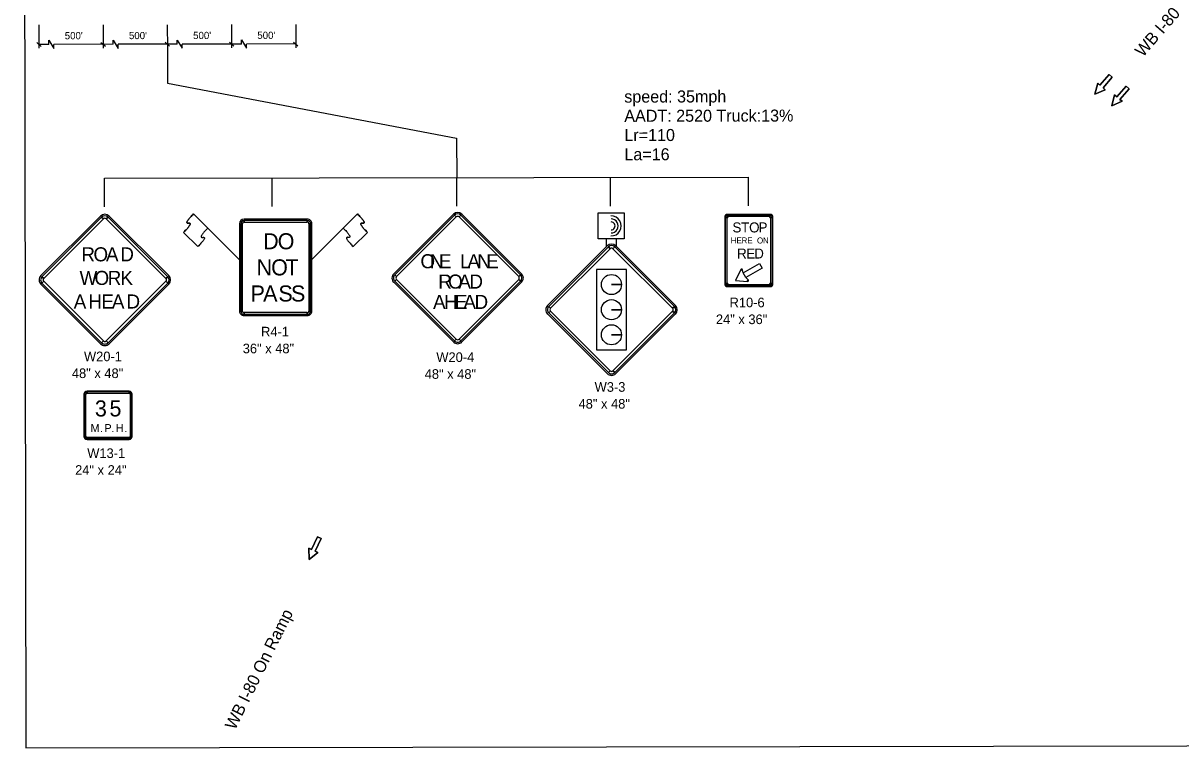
# Model space of a CAD drawing. Extents: x 16513048 to 16518780, y 7009856 to 7010869.
# Drawn here: x 16515047 to 16515769, y 7009856 to 7010308 of the extents above; entities that cross this region are included whole.
import ezdxf

# ---------------------------------------------------------------- set-up
doc = ezdxf.new("R2010")
doc.units = 0
for name, color, linetype in [('Dimensions', 7, 'Continuous'), ('dsnNonPlotable', 7, 'Continuous'), ('dsnStdLabel', 7, 'Continuous'), ('Level 2', 7, 'Continuous'), ('Level 5', 7, 'Continuous'), ('NamedBoundary', 7, 'Continuous')]:
    doc.layers.add(name, color=color, linetype=linetype)

msp = doc.modelspace()

# ---------------------------------------------------------------- linework, layer by layer
at = {"layer": 'dsnStdLabel'}
for p, q in [((16515095.65, 7010187.98), (16515058.47, 7010150.8)), ((16515096.31, 7010187.31), (16515097.42, 7010186.21)), ((16515099.19, 7010186.21), (16515100.3, 7010187.31)), ((16515138.14, 7010150.8), (16515100.96, 7010187.98)), ((16515182.3, 7010160.59), (16515153.59, 7010189.28)), ((16515153.59, 7010189.28), (16515162.44, 7010180.43)), ((16515182.23, 7010183.19), (16515182.23, 7010128.73)), ((16515183.01, 7010183.19), (16515184.11, 7010183.19)), ((16515224.48, 7010186), (16515185.05, 7010186)), ((16515185.05, 7010184.13), (16515185.05, 7010185.22)), ((16515224.48, 7010185.22), (16515224.48, 7010184.13)), ((16515225.42, 7010183.19), (16515226.51, 7010183.19)), ((16515227.01, 7010160.59), (16515255.71, 7010189.29)), ((16515227.29, 7010128.73), (16515227.29, 7010183.19)), ((16515255.71, 7010189.29), (16515246.85, 7010180.43)), ((16515315.5, 7010189.14), (16515278.32, 7010151.96)), ((16515316.17, 7010188.47), (16515317.27, 7010187.37)), ((16515319.04, 7010187.37), (16515320.15, 7010188.47)), ((16515357.99, 7010151.96), (16515320.81, 7010189.14)), ((16515484.59, 7010187.12), (16515486.47, 7010187.12)), ((16515485.06, 7010187.12), (16515485.84, 7010187.12)), ((16515486.47, 7010187.12), (16515486.47, 7010189)), ((16515486.47, 7010187.75), (16515486.47, 7010188.53)), ((16515512.75, 7010189), (16515512.75, 7010187.12)), ((16515512.75, 7010188.53), (16515512.75, 7010187.75)), ((16515512.75, 7010187.12), (16515514.63, 7010187.12)), ((16515513.38, 7010187.12), (16515514.16, 7010187.12)), ((16515156.25, 7010168.92), (16515147.39, 7010177.77)), ((16515253.06, 7010168.92), (16515261.91, 7010177.78)), ((16515411.4, 7010169.38), (16515374.22, 7010132.2)), ((16515453.89, 7010132.2), (16515416.71, 7010169.38)), ((16515412.06, 7010168.71), (16515413.17, 7010167.61)), ((16515414.94, 7010167.61), (16515416.04, 7010168.71)), ((16515494.53, 7010154.59), (16515495.09, 7010154.29)), ((16515495.09, 7010154.29), (16515495.7, 7010154.43)), ((16515060.24, 7010149.03), (16515059.14, 7010150.14)), ((16515059.14, 7010146.15), (16515060.24, 7010147.26)), ((16515137.47, 7010150.14), (16515136.37, 7010149.03)), ((16515136.37, 7010147.26), (16515137.47, 7010146.15)), ((16515280.09, 7010150.19), (16515278.99, 7010151.3)), ((16515278.99, 7010147.31), (16515280.09, 7010148.42)), ((16515357.32, 7010151.3), (16515356.22, 7010150.19)), ((16515356.22, 7010148.42), (16515357.32, 7010147.31)), ((16515498.84, 7010147.79), (16515498.82, 7010147.16)), ((16515499.27, 7010148.25), (16515498.84, 7010147.79)), ((16515058.47, 7010145.49), (16515095.65, 7010108.31)), ((16515100.96, 7010108.31), (16515138.14, 7010145.49)), ((16515278.32, 7010146.65), (16515315.5, 7010109.47)), ((16515320.81, 7010109.47), (16515357.99, 7010146.65)), ((16515420.27, 7010145.23), (16515414.01, 7010145.23)), ((16515414.01, 7010145.23), (16515420.27, 7010145.23)), ((16515486.47, 7010145.81), (16515484.59, 7010145.81)), ((16515485.84, 7010145.81), (16515485.06, 7010145.81)), ((16515486.47, 7010143.94), (16515486.47, 7010145.81)), ((16515486.47, 7010144.41), (16515486.47, 7010145.19)), ((16515514.63, 7010145.81), (16515512.75, 7010145.81)), ((16515512.75, 7010145.81), (16515512.75, 7010143.94)), ((16515512.75, 7010145.19), (16515512.75, 7010144.41)), ((16515514.16, 7010145.81), (16515513.38, 7010145.81)), ((16515184.11, 7010128.73), (16515183.01, 7010128.73)), ((16515185.05, 7010126.7), (16515185.05, 7010127.8)), ((16515185.05, 7010125.92), (16515224.48, 7010125.92)), ((16515224.48, 7010127.8), (16515224.48, 7010126.7)), ((16515226.51, 7010128.73), (16515225.42, 7010128.73)), ((16515374.22, 7010126.89), (16515411.4, 7010089.71)), ((16515375.99, 7010130.43), (16515374.88, 7010131.53)), ((16515374.88, 7010127.55), (16515375.99, 7010128.66)), ((16515420.27, 7010129.58), (16515414.01, 7010129.58)), ((16515414.01, 7010129.58), (16515420.27, 7010129.58)), ((16515416.71, 7010089.71), (16515453.89, 7010126.89)), ((16515453.22, 7010131.53), (16515452.12, 7010130.43)), ((16515452.12, 7010128.66), (16515453.22, 7010127.55)), ((16515317.27, 7010111.24), (16515316.17, 7010110.14)), ((16515320.15, 7010110.14), (16515319.04, 7010111.24)), ((16515420.27, 7010113.93), (16515414.01, 7010113.93)), ((16515414.01, 7010113.93), (16515420.27, 7010113.93)), ((16515097.42, 7010110.08), (16515096.31, 7010108.98)), ((16515100.3, 7010108.98), (16515099.19, 7010110.08)), ((16515413.17, 7010091.48), (16515412.06, 7010090.37)), ((16515416.04, 7010090.37), (16515414.94, 7010091.48)), ((16515085.31, 7010076.88), (16515085.31, 7010050.59)), ((16515085.78, 7010076.88), (16515086.56, 7010076.88)), ((16515113.48, 7010078.76), (16515087.19, 7010078.76)), ((16515087.19, 7010077.51), (16515087.19, 7010078.29)), ((16515113.48, 7010078.29), (16515113.48, 7010077.51)), ((16515114.1, 7010076.88), (16515114.88, 7010076.88)), ((16515115.35, 7010050.59), (16515115.35, 7010076.88)), ((16515086.56, 7010050.59), (16515085.78, 7010050.59)), ((16515087.19, 7010049.19), (16515087.19, 7010049.97)), ((16515087.19, 7010048.72), (16515113.48, 7010048.72)), ((16515113.48, 7010049.97), (16515113.48, 7010049.19)), ((16515114.88, 7010050.59), (16515114.1, 7010050.59))]:
    msp.add_line(p, q, dxfattribs=at)
for points in [[(16515096.31, 7010187.31), (16515059.14, 7010150.14), (16515060.24, 7010149.03), (16515097.42, 7010186.21), (16515096.31, 7010187.31)], [(16515137.47, 7010150.14), (16515100.3, 7010187.31), (16515099.19, 7010186.21), (16515136.37, 7010149.03), (16515137.47, 7010150.14)], [(16515183.01, 7010183.19), (16515183.01, 7010128.73), (16515184.11, 7010128.73), (16515184.11, 7010183.19), (16515183.01, 7010183.19)], [(16515224.48, 7010185.22), (16515185.05, 7010185.22), (16515185.05, 7010184.13), (16515224.48, 7010184.13), (16515224.48, 7010185.22)], [(16515226.51, 7010128.73), (16515226.51, 7010183.19), (16515225.42, 7010183.19), (16515225.42, 7010128.73), (16515226.51, 7010128.73)], [(16515316.17, 7010188.47), (16515278.99, 7010151.3), (16515280.09, 7010150.19), (16515317.27, 7010187.37), (16515316.17, 7010188.47)], [(16515357.32, 7010151.3), (16515320.15, 7010188.47), (16515319.04, 7010187.37), (16515356.22, 7010150.19), (16515357.32, 7010151.3)], [(16515486.47, 7010143.94), (16515512.75, 7010143.94), (16515512.75, 7010145.81), (16515514.63, 7010145.81), (16515514.63, 7010187.12), (16515512.75, 7010187.12), (16515512.75, 7010189), (16515486.47, 7010189), (16515486.47, 7010187.12), (16515484.59, 7010187.12), (16515484.59, 7010145.81), (16515486.47, 7010145.81), (16515486.47, 7010143.94)], [(16515485.84, 7010187.12), (16515485.84, 7010145.81), (16515485.06, 7010145.81), (16515485.06, 7010187.12), (16515485.84, 7010187.12)], [(16515512.75, 7010187.75), (16515486.47, 7010187.75), (16515486.47, 7010188.53), (16515512.75, 7010188.53), (16515512.75, 7010187.75)], [(16515513.38, 7010145.81), (16515513.38, 7010187.12), (16515514.16, 7010187.12), (16515514.16, 7010145.81), (16515513.38, 7010145.81)], [(16515412.06, 7010168.71), (16515374.88, 7010131.53), (16515375.99, 7010130.43), (16515413.17, 7010167.61), (16515412.06, 7010168.71)], [(16515453.22, 7010131.53), (16515416.04, 7010168.71), (16515414.94, 7010167.61), (16515452.12, 7010130.43), (16515453.22, 7010131.53)], [(16515423.43, 7010154.55), (16515404.67, 7010154.55), (16515404.67, 7010104.53), (16515423.43, 7010104.53), (16515423.43, 7010154.55)], [(16515491.27, 7010147.76), (16515498.82, 7010147.16), (16515498.84, 7010147.79), (16515499.27, 7010148.25), (16515497.78, 7010149.62), (16515496.14, 7010152.46), (16515495.7, 7010154.43), (16515495.09, 7010154.29), (16515494.53, 7010154.59), (16515491.27, 7010147.76)], [(16515506.31, 7010158.33), (16515507.95, 7010155.49), (16515497.78, 7010149.62), (16515496.14, 7010152.46), (16515506.31, 7010158.33)], [(16515059.14, 7010146.15), (16515096.31, 7010108.98), (16515097.42, 7010110.08), (16515060.24, 7010147.26), (16515059.14, 7010146.15)], [(16515100.3, 7010108.98), (16515137.47, 7010146.15), (16515136.37, 7010147.26), (16515099.19, 7010110.08), (16515100.3, 7010108.98)], [(16515278.99, 7010147.31), (16515316.17, 7010110.14), (16515317.27, 7010111.24), (16515280.09, 7010148.42), (16515278.99, 7010147.31)], [(16515320.15, 7010110.14), (16515357.32, 7010147.31), (16515356.22, 7010148.42), (16515319.04, 7010111.24), (16515320.15, 7010110.14)], [(16515486.47, 7010145.19), (16515512.75, 7010145.19), (16515512.75, 7010144.41), (16515486.47, 7010144.41), (16515486.47, 7010145.19)], [(16515185.05, 7010126.7), (16515224.48, 7010126.7), (16515224.48, 7010127.8), (16515185.05, 7010127.8), (16515185.05, 7010126.7)], [(16515374.88, 7010127.55), (16515412.06, 7010090.37), (16515413.17, 7010091.48), (16515375.99, 7010128.66), (16515374.88, 7010127.55)], [(16515416.04, 7010090.37), (16515453.22, 7010127.55), (16515452.12, 7010128.66), (16515414.94, 7010091.48), (16515416.04, 7010090.37)], [(16515085.78, 7010076.88), (16515085.78, 7010050.59), (16515086.56, 7010050.59), (16515086.56, 7010076.88), (16515085.78, 7010076.88)], [(16515113.48, 7010078.29), (16515087.19, 7010078.29), (16515087.19, 7010077.51), (16515113.48, 7010077.51), (16515113.48, 7010078.29)], [(16515114.88, 7010050.59), (16515114.88, 7010076.88), (16515114.1, 7010076.88), (16515114.1, 7010050.59), (16515114.88, 7010050.59)], [(16515087.19, 7010049.19), (16515113.48, 7010049.19), (16515113.48, 7010049.97), (16515087.19, 7010049.97), (16515087.19, 7010049.19)]]:
    msp.add_lwpolyline(points, close=True, dxfattribs=at)
for centre in [(16515414.01, 7010145.23), (16515414.01, 7010129.58), (16515414.01, 7010113.93)]:
    msp.add_circle(centre, 6.26, dxfattribs=at)
for centre, radius, start, end in [((16515098.3, 7010185.32), 3.76, 44.99999, 134.99974), ((16515098.3, 7010185.32), 2.82, 44.99999, 134.99974), ((16515098.3, 7010185.32), 1.25, 44.99999, 134.99974), ((16515185.05, 7010183.19), 2.82, 90.00021, 179.99985), ((16515185.05, 7010183.19), 2.03, 90.00021, 179.99985), ((16515185.05, 7010183.19), 0.939, 90.00021, 179.99985), ((16515224.48, 7010183.19), 2.82, 0, 90.00021), ((16515224.48, 7010183.19), 2.03, 0, 90.00021), ((16515224.48, 7010183.19), 0.939, 0, 90.00021), ((16515318.16, 7010186.48), 3.76, 44.99999, 134.99974), ((16515318.16, 7010186.48), 2.82, 44.99999, 134.99974), ((16515318.16, 7010186.48), 1.25, 44.99999, 134.99974), ((16515486.47, 7010187.12), 1.88, 90.00021, 179.99985), ((16515486.47, 7010187.12), 1.41, 90.00021, 179.99985), ((16515486.47, 7010187.12), 0.626, 90.00021, 179.99985), ((16515512.75, 7010187.12), 1.88, 0, 90.00021), ((16515512.75, 7010187.12), 1.41, 0, 90.00021), ((16515512.75, 7010187.12), 0.626, 0, 90.00021), ((16515414.05, 7010166.72), 3.76, 44.99999, 134.99974), ((16515414.05, 7010166.72), 2.82, 44.99999, 134.99974), ((16515414.05, 7010166.72), 1.25, 44.99999, 134.99974), ((16515495.09, 7010154.29), 0.626, 12.62232, 152.27557), ((16515061.13, 7010148.14), 3.76, 134.99974, 224.99995), ((16515061.13, 7010148.14), 2.82, 134.99974, 224.99995), ((16515061.13, 7010148.14), 1.25, 134.99974, 224.99995), ((16515135.48, 7010148.14), 1.25, 315.00016, 44.9998), ((16515135.48, 7010148.14), 2.82, 315.00016, 44.9998), ((16515135.48, 7010148.14), 3.76, 315.00016, 44.9998), ((16515280.98, 7010149.31), 3.76, 134.99974, 224.99995), ((16515280.98, 7010149.31), 2.82, 134.99974, 224.99995), ((16515280.98, 7010149.31), 1.25, 134.99974, 224.99995), ((16515355.33, 7010149.31), 1.25, 315.00016, 44.9998), ((16515355.33, 7010149.31), 2.82, 315.00016, 44.9998), ((16515355.33, 7010149.31), 3.76, 315.00016, 44.9998), ((16515498.84, 7010147.79), 0.626, 267.72427, 47.37758), ((16515486.47, 7010145.81), 1.88, 179.99985, 270.00006), ((16515486.47, 7010145.81), 1.41, 179.99985, 270.00006), ((16515486.47, 7010145.81), 0.626, 179.99985, 270.00006), ((16515512.75, 7010145.81), 1.88, 270.00006, 0.00027), ((16515512.75, 7010145.81), 1.41, 270.00006, 0.00027), ((16515512.75, 7010145.81), 0.626, 270.00006, 0.00027), ((16515185.05, 7010128.73), 2.82, 179.99985, 270.00006), ((16515185.05, 7010128.73), 2.03, 179.99985, 270.00006), ((16515185.05, 7010128.73), 0.939, 179.99985, 270.00006), ((16515224.48, 7010128.73), 2.82, 270.00006, 0.00027), ((16515224.48, 7010128.73), 2.03, 270.00006, 0.00027), ((16515224.48, 7010128.73), 0.939, 270.00006, 0.00027), ((16515376.88, 7010129.54), 3.76, 134.99974, 224.99995), ((16515376.88, 7010129.54), 2.82, 134.99974, 224.99995), ((16515376.88, 7010129.54), 1.25, 134.99974, 224.99995), ((16515451.23, 7010129.54), 1.25, 315.00016, 44.9998), ((16515451.23, 7010129.54), 2.82, 315.00016, 44.9998), ((16515451.23, 7010129.54), 3.76, 315.00016, 44.9998), ((16515318.16, 7010112.13), 1.25, 224.99995, 315.00016), ((16515098.3, 7010110.97), 3.76, 224.99995, 315.00016), ((16515098.3, 7010110.97), 2.82, 224.99995, 315.00016), ((16515098.3, 7010110.97), 1.25, 224.99995, 315.00016), ((16515318.16, 7010112.13), 3.76, 224.99995, 315.00016), ((16515318.16, 7010112.13), 2.82, 224.99995, 315.00016), ((16515414.05, 7010092.37), 3.76, 224.99995, 315.00016), ((16515414.05, 7010092.37), 2.82, 224.99995, 315.00016), ((16515414.05, 7010092.37), 1.25, 224.99995, 315.00016), ((16515087.19, 7010076.88), 1.88, 90.00021, 179.99985), ((16515087.19, 7010076.88), 1.41, 90.00021, 179.99985), ((16515087.19, 7010076.88), 0.626, 90.00021, 179.99985), ((16515113.48, 7010076.88), 1.88, 0, 90.00021), ((16515113.48, 7010076.88), 1.41, 0, 90.00021), ((16515113.48, 7010076.88), 0.626, 0, 90.00021), ((16515087.19, 7010050.59), 1.88, 179.99985, 270.00006), ((16515087.19, 7010050.59), 1.41, 179.99985, 270.00006), ((16515087.19, 7010050.59), 0.626, 179.99985, 270.00006), ((16515113.48, 7010050.59), 1.88, 270.00006, 0.00027), ((16515113.48, 7010050.59), 1.41, 270.00006, 0.00027), ((16515113.48, 7010050.59), 0.626, 270.00006, 0.00027)]:
    msp.add_arc(centre, radius, start, end, dxfattribs=at)
for points in [[(16515147.39, 7010177.77), (16515153.59, 7010183.96), (16515147.39, 7010183.08), (16515153.59, 7010189.28)], [(16515261.91, 7010177.78), (16515255.71, 7010183.97), (16515261.91, 7010183.09), (16515255.71, 7010189.29)], [(16515162.44, 7010180.43), (16515156.25, 7010174.23), (16515162.44, 7010175.11), (16515156.25, 7010168.92)], [(16515246.85, 7010180.43), (16515253.05, 7010174.23), (16515246.86, 7010175.12), (16515253.06, 7010168.92)]]:
    msp.add_open_spline(points, degree=2, dxfattribs=at)
at = {"layer": 'Level 2'}
for p, q in [((16515057.23, 7010307.08), (16515057.26, 7010292.53)), ((16515097.23, 7010307.15), (16515097.25, 7010292.6)), ((16515137.23, 7010307.22), (16515137.25, 7010292.66)), ((16515177.23, 7010307.29), (16515177.25, 7010292.73)), ((16515217.23, 7010307.36), (16515217.25, 7010292.8)), ((16515055.88, 7010296.13), (16515058.63, 7010293.75)), ((16515063.42, 7010294.95), (16515057.25, 7010294.94)), ((16515103.42, 7010295.02), (16515066.58, 7010294.96)), ((16515095.88, 7010296.2), (16515098.63, 7010293.82)), ((16515143.42, 7010295.09), (16515106.58, 7010295.03)), ((16515135.88, 7010296.27), (16515138.63, 7010293.89)), ((16515137.25, 7010292.66), (16515137.29, 7010270.71)), ((16515183.42, 7010295.16), (16515146.58, 7010295.1)), ((16515175.88, 7010296.34), (16515178.63, 7010293.96)), ((16515217.25, 7010295.22), (16515186.58, 7010295.17)), ((16515215.88, 7010296.41), (16515218.63, 7010294.03)), ((16515137.29, 7010270.71), (16515317.53, 7010236.52)), ((16515317.53, 7010236.52), (16515317.57, 7010211.85)), ((16515098.08, 7010211.47), (16515499.38, 7010212.17)), ((16515413.49, 7010194.22), (16515413.46, 7010212.02)), ((16515499.41, 7010194.37), (16515499.38, 7010212.17)), ((16515098.11, 7010193.67), (16515098.08, 7010211.47)), ((16515202.54, 7010193.85), (16515202.51, 7010211.65)), ((16515317.6, 7010194.05), (16515317.57, 7010211.85)), ((16515410.63, 7010173.66), (16515410.63, 7010168.65)), ((16515416.89, 7010173.66), (16515416.89, 7010168.65))]:
    msp.add_line(p, q, dxfattribs=at)
for points in [[(16515063.42, 7010294.96), (16515063.42, 7010297.51), (16515066.58, 7010292.4), (16515066.58, 7010294.96)], [(16515103.42, 7010295.03), (16515103.42, 7010297.58), (16515106.58, 7010292.47), (16515106.58, 7010295.03)], [(16515143.42, 7010295.1), (16515143.42, 7010297.65), (16515146.58, 7010292.54), (16515146.58, 7010295.1)], [(16515183.42, 7010295.17), (16515183.42, 7010297.72), (16515186.58, 7010292.61), (16515186.58, 7010295.17)]]:
    msp.add_lwpolyline(points, dxfattribs=at)
for points in [[(16515724.1, 7010276.23), (16515726, 7010274.6), (16515720.31, 7010267.95), (16515721.73, 7010266.73), (16515715.29, 7010264.02), (16515716.99, 7010270.8), (16515718.41, 7010269.58)], [(16515734.66, 7010268.97), (16515736.56, 7010267.34), (16515730.86, 7010260.7), (16515732.29, 7010259.48), (16515725.85, 7010256.76), (16515727.54, 7010263.54), (16515728.96, 7010262.32)], [(16515405.62, 7010173.66), (16515405.62, 7010189.93), (16515421.89, 7010189.93), (16515421.89, 7010173.66)], [(16515230.75, 7009987.95), (16515233.02, 7009986.9), (16515229.34, 7009978.96), (16515231.04, 7009978.17), (16515225.57, 7009973.81), (16515225.37, 7009980.8), (16515227.07, 7009980.01)]]:
    msp.add_lwpolyline(points, close=True, dxfattribs=at)
for radius in [6.26, 6.26, 4.38, 2.5]:
    msp.add_arc((16515413.76, 7010181.79), radius, 269.40414, 90.54446, dxfattribs=at)
at = {"layer": 'Level 5'}
for p, q in [((16515147.39, 7010177.77), (16515156.25, 7010168.92)), ((16515261.91, 7010177.78), (16515253.06, 7010168.92))]:
    msp.add_line(p, q, dxfattribs=at)
for points in [[(16515718.41, 7010269.58), (16515716.99, 7010270.8), (16515715.29, 7010264.02), (16515721.73, 7010266.73), (16515720.31, 7010267.95), (16515726, 7010274.6), (16515724.1, 7010276.23), (16515718.41, 7010269.58)], [(16515728.96, 7010262.32), (16515727.54, 7010263.54), (16515725.85, 7010256.76), (16515732.29, 7010259.48), (16515730.86, 7010260.7), (16515736.56, 7010267.34), (16515734.66, 7010268.97), (16515728.96, 7010262.32)], [(16515227.07, 7009980.01), (16515225.37, 7009980.8), (16515225.57, 7009973.81), (16515231.04, 7009978.17), (16515229.34, 7009978.96), (16515233.02, 7009986.9), (16515230.75, 7009987.95), (16515227.07, 7009980.01)]]:
    msp.add_lwpolyline(points, dxfattribs=at)
for points in [[(16515153.59, 7010189.28), (16515147.39, 7010183.08), (16515153.59, 7010183.96), (16515147.39, 7010177.77)], [(16515255.71, 7010189.29), (16515261.91, 7010183.09), (16515255.71, 7010183.97), (16515261.91, 7010177.78)], [(16515162.44, 7010180.43), (16515156.25, 7010174.23), (16515162.44, 7010175.11), (16515156.25, 7010168.92)], [(16515246.85, 7010180.43), (16515253.05, 7010174.23), (16515246.86, 7010175.12), (16515253.06, 7010168.92)]]:
    msp.add_open_spline(points, degree=2, dxfattribs=at)
at = {"layer": 'NamedBoundary'}
msp.add_lwpolyline([(16515047.4, 7010866.4), (16515049.16, 7009856.4), (16516616.66, 7009859.13), (16516614.9, 7010869.13)], close=True, dxfattribs=at)

# ---------------------------------------------------------------- texts
at = {"layer": 'Dimensions'}
for s, rotation, p in [('WB I-80', 49.18036, (16515745.21, 7010286.65)), ('WB I-80 On Ramp', 63.63415, (16515179.45, 7009867.1))]:
    msp.add_text(s, height=7.5, rotation=rotation, dxfattribs=at).set_placement(p)
at = {"layer": 'dsnNonPlotable'}
for s, p in [('speed: 35mph', (16515421.99, 7010258.68)), ('AADT: 2520 Truck:13%', (16515422.01, 7010246.68)), ('Lr=110', (16515422.04, 7010234.68)), ('La=16', (16515422.06, 7010222.68))]:
    msp.add_text(s, height=7.5, rotation=0.09989, dxfattribs=at).set_placement(p)
at = {"layer": 'dsnStdLabel'}
for s, height, p in [('S', 6.26, (16515489.37, 7010177.74)), ('T', 6.26, (16515494.76, 7010177.74)), ('O', 6.26, (16515499.76, 7010177.74)), ('P', 6.26, (16515505.64, 7010177.74)), ('D', 10.01, (16515196.94, 7010167.23)), ('O', 10.01, (16515206.01, 7010167.23)), ('H', 3.76, (16515488.33, 7010170.85)), ('E', 3.76, (16515491.91, 7010170.85)), ('R', 3.76, (16515495.05, 7010170.85)), ('E', 3.76, (16515498.62, 7010170.85)), ('O', 3.76, (16515504.67, 7010170.85)), ('N', 3.76, (16515508.37, 7010170.85)), ('R', 8.76, (16515083.7, 7010159.72)), ('O', 8.76, (16515091.22, 7010159.72)), ('A', 8.76, (16515099.01, 7010159.72)), ('D', 8.76, (16515107.96, 7010159.72)), ('O', 8.76, (16515294.98, 7010155.41)), ('N', 8.76, (16515300.88, 7010155.41)), ('E', 8.76, (16515306.5, 7010155.41)), ('L', 8.76, (16515319.64, 7010155.41)), ('A', 8.76, (16515324.25, 7010155.41)), ('N', 8.76, (16515330.39, 7010155.41)), ('E', 8.76, (16515336.01, 7010155.41)), ('R', 6.26, (16515492.26, 7010161.46)), ('E', 6.26, (16515497.93, 7010161.46)), ('D', 6.26, (16515502.92, 7010161.46)), ('N', 10.01, (16515192.87, 7010150.95)), ('O', 10.01, (16515201.95, 7010150.95)), ('T', 10.01, (16515210.86, 7010150.95)), ('W', 8.76, (16515082.56, 7010145.01)), ('O', 8.76, (16515091.87, 7010145.01)), ('R', 8.76, (16515100.09, 7010145.01)), ('K', 8.76, (16515108.03, 7010145.01)), ('R', 8.76, (16515306.05, 7010142.73)), ('O', 8.76, (16515312.2, 7010142.73)), ('A', 8.76, (16515318.63, 7010142.73)), ('D', 8.76, (16515325.47, 7010142.73)), ('P', 10.01, (16515189.11, 7010134.68)), ('A', 10.01, (16515196.96, 7010134.68)), ('S', 10.01, (16515206.46, 7010134.68)), ('S', 10.01, (16515214.31, 7010134.68)), ('A', 8.76, (16515078.92, 7010130.31)), ('H', 8.76, (16515088.03, 7010130.31)), ('E', 8.76, (16515096.16, 7010130.31)), ('A', 8.76, (16515102.69, 7010130.31)), ('D', 8.76, (16515111.81, 7010130.31)), ('A', 8.76, (16515302.83, 7010130.06)), ('H', 8.76, (16515309.77, 7010130.06)), ('E', 8.76, (16515316.39, 7010130.06)), ('A', 8.76, (16515321.75, 7010130.06)), ('D', 8.76, (16515328.69, 7010130.06)), ('R10-6', 6, (16515487.59, 7010131.08)), ('24" x 36"', 6, (16515479.08, 7010120.58)), ('R4-1', 6, (16515195.66, 7010112.89)), ('36" x 48"', 6, (16515184.23, 7010102.39)), ('W20-1', 6, (16515085.31, 7010097.45)), ('W20-4', 6, (16515304.87, 7010096.98)), ('48" x 48"', 6, (16515077.76, 7010086.95)), ('48" x 48"', 6, (16515297.62, 7010086.48)), ('W3-3', 6, (16515403.51, 7010078.4)), ('3', 10.01, (16515092.12, 7010063.01)), ('5', 10.01, (16515101.2, 7010063.01)), ('48" x 48"', 6, (16515393.49, 7010067.9)), ('M', 5.01, (16515089.43, 7010053.25)), ('.', 5.01, (16515095.33, 7010053.25)), ('P', 5.01, (16515098.07, 7010053.25)), ('.', 5.01, (16515102.4, 7010053.25)), ('H', 5.01, (16515105.14, 7010053.25)), ('.', 5.01, (16515110.38, 7010053.25)), ('W13-1', 6, (16515087.34, 7010037.12)), ('24" x 24"', 6, (16515079.79, 7010026.62))]:
    msp.add_text(s, height=height, dxfattribs=at).set_placement(p)
at = {"layer": 'Level 2'}
for p in [(16515073.33, 7010298.17), (16515113.33, 7010298.24), (16515153.33, 7010298.31), (16515193.33, 7010298.38)]:
    msp.add_text("500'", height=4.5, dxfattribs=at).set_placement(p)

doc.saveas('drawing.dxf')
